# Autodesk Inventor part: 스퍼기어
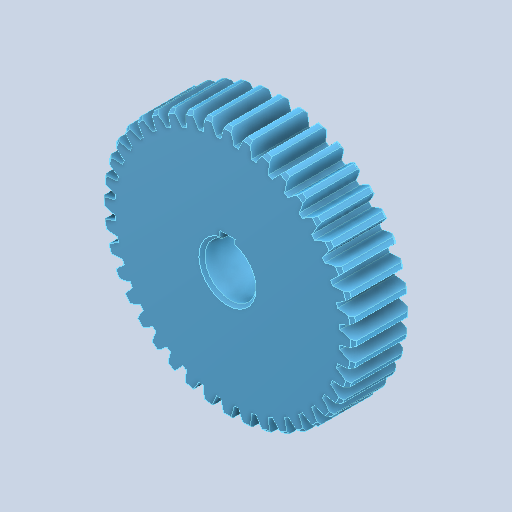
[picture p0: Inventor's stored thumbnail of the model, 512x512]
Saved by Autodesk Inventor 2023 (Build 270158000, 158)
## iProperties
Created: 2025-03
Part Number: 스퍼기어
Material: 알루미늄 6061
Document SubType Name: Modeling
Designer: Admin
Density: 2.71 g/cm^3
Appearance: 기본값
Author: jhkim
Sending System: Autodesk Inventor 2025
Preprocessor: ST-DEVELOPER v20
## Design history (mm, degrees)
feature "Solid1"
node "솔리드1"
